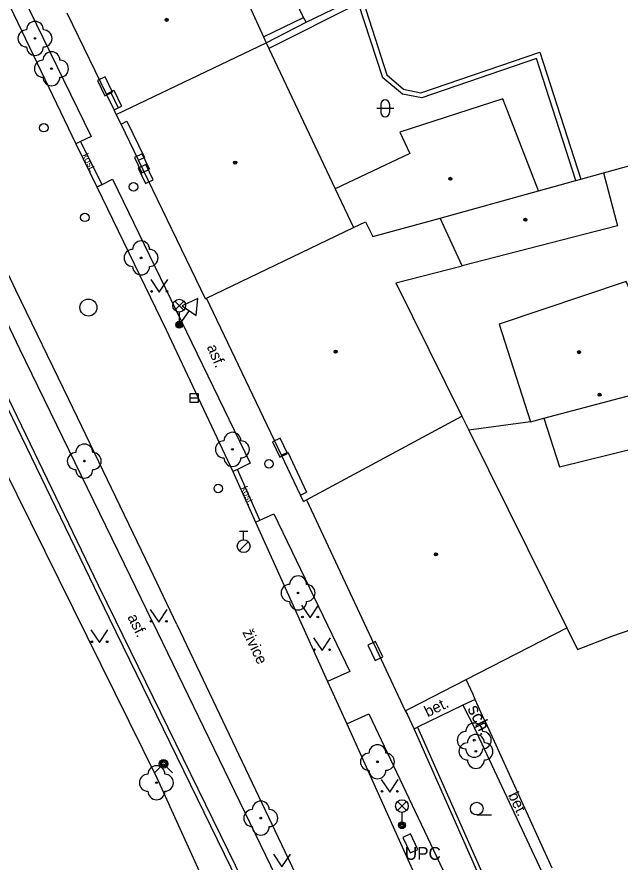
# Model space of a CAD drawing. Extents: x -595546 to -593986, y -1160845 to -1159202.
# Drawn here: x -595415.64 to -595380.17, y -1160258.12 to -1160208.45 of the extents above; entities that cross this region are included whole.
import ezdxf

# ---------------------------------------------------------------- set-up
doc = ezdxf.new("R2010")
doc.units = 0
for name, color, linetype in [('DOP - kresba z DSPS bez souradnic', 7, 'Continuous'), ('DOP - rozhrani ploch obecne', 7, 'Continuous'), ('Level 22', 7, 'Continuous'), ('Level 24', 7, 'Continuous'), ('Level 27', 7, 'Continuous'), ('Level 28', 7, 'Continuous'), ('Level 31', 7, 'Continuous'), ('Level 33', 7, 'Continuous'), ('Level 34', 7, 'Continuous'), ('Level 36', 7, 'Continuous'), ('Level 39', 7, 'Continuous'), ('TM - budovy zdene_ betonove - NP', 7, 'Continuous'), ('TM - budovy zdene_ betonove - VP', 7, 'Continuous'), ('TM - chodniky - VP', 7, 'Continuous'), ('TM - komunikace - VP', 7, 'Continuous'), ('TM - letecke snimky - pomocna linie', 7, 'Continuous'), ('TM - plot drateny_ kovovy - VP', 7, 'Continuous'), ('TM - plot nerozliseny - VP', 7, 'Continuous'), ('TM - podezdivka plotu - VP', 7, 'Continuous'), ('TM - popis objektu', 7, 'Continuous'), ('TM - popis povrchu', 7, 'Continuous'), ('TM - poznamka', 7, 'Continuous'), ('TM - rozhrani mezi zpev. plochami mezi sebou - VP', 7, 'Continuous'), ('TM - rozhrani ploch obecne - VP', 7, 'Continuous'), ('TM - schody - NP', 7, 'Continuous'), ('TM - vjezd na pozemek', 7, 'Continuous')]:
    doc.layers.add(name, color=color, linetype=linetype)

msp = doc.modelspace()

# ---------------------------------------------------------------- linework, layer by layer
at = {"layer": 'DOP - kresba z DSPS bez souradnic'}
for points in [[(-595398.78, -1160208.48), (-595401.52, -1160202.77)], [(-595395.55, -1160207.66), (-595400.82, -1160210.3)], [(-595394.13, -1160212.03), (-595395.55, -1160207.66)], [(-595401.14, -1160209.62), (-595398.78, -1160208.48)], [(-595398.64, -1160208.76), (-595398.78, -1160208.48)], [(-595385.08, -1160210.89), (-595391.83, -1160213.2)], [(-595382.77, -1160218.07), (-595385.08, -1160210.89)], [(-595392.96, -1160212.98), (-595394.13, -1160212.03)], [(-595391.83, -1160213.2), (-595392.96, -1160212.98)]]:
    msp.add_lwpolyline(points, dxfattribs=at)
at = {"layer": 'DOP - rozhrani ploch obecne'}
for points in [[(-595398.64, -1160208.76), (-595395.41, -1160207.19)], [(-595395.28, -1160207.53), (-595393.89, -1160211.85)], [(-595400.98, -1160209.97), (-595398.64, -1160208.76)], [(-595391.89, -1160212.91), (-595384.89, -1160210.51)], [(-595384.89, -1160210.51), (-595382.47, -1160217.99)], [(-595393.89, -1160211.85), (-595392.9, -1160212.69)], [(-595392.9, -1160212.69), (-595391.89, -1160212.91)], [(-595381.14, -1160217.61), (-595377.66, -1160216.65)]]:
    msp.add_lwpolyline(points, dxfattribs=at)
at = {"layer": 'Level 22'}
for centre in [(-595414.58, -1160209.71), (-595413.61, -1160211.49), (-595408.34, -1160222.61), (-595402.97, -1160233.86), (-595411.68, -1160234.55), (-595399.11, -1160242.3), (-595388.75, -1160250.95), (-595388.65, -1160251.61), (-595394.44, -1160252.22), (-595407.44, -1160253.45), (-595401.3, -1160255.53)]:
    msp.add_circle(centre, 0.05, dxfattribs=at)
for centre, start, end in [((-595414.58, -1160209.21), 0, 180), ((-595415.08, -1160209.71), 90, 270), ((-595414.08, -1160209.71), 270, 90), ((-595414.58, -1160210.21), 180, 0), ((-595413.61, -1160210.99), 0, 180), ((-595414.11, -1160211.49), 90, 270), ((-595413.11, -1160211.49), 270, 90), ((-595413.61, -1160211.99), 180, 0), ((-595408.34, -1160222.11), 0, 180), ((-595408.84, -1160222.61), 90, 270), ((-595407.84, -1160222.61), 270, 90), ((-595408.34, -1160223.11), 180, 0), ((-595402.97, -1160233.36), 0, 180), ((-595411.68, -1160234.05), 0, 180), ((-595403.47, -1160233.86), 90, 270), ((-595402.47, -1160233.86), 270, 90), ((-595412.18, -1160234.55), 90, 270), ((-595411.18, -1160234.55), 270, 90), ((-595402.97, -1160234.36), 180, 0), ((-595411.68, -1160235.05), 180, 0), ((-595399.11, -1160241.8), 0, 180), ((-595399.61, -1160242.3), 90, 270), ((-595398.61, -1160242.3), 270, 90), ((-595399.11, -1160242.8), 180, 0), ((-595388.75, -1160250.45), 0, 180), ((-595389.25, -1160250.95), 90, 270), ((-595388.25, -1160250.95), 270, 90), ((-595388.65, -1160251.11), 0, 180), ((-595394.44, -1160251.72), 0, 180), ((-595389.15, -1160251.61), 90, 270), ((-595388.75, -1160251.45), 180, 0), ((-595388.15, -1160251.61), 270, 90), ((-595394.94, -1160252.22), 90, 270), ((-595393.94, -1160252.22), 270, 90), ((-595407.44, -1160252.95), 0, 180), ((-595388.65, -1160252.11), 180, 0), ((-595407.94, -1160253.45), 90, 270), ((-595406.94, -1160253.45), 270, 90), ((-595394.44, -1160252.72), 180, 0), ((-595407.44, -1160253.95), 180, 0), ((-595401.3, -1160255.03), 0, 180), ((-595401.8, -1160255.53), 90, 270), ((-595400.8, -1160255.53), 270, 90), ((-595401.3, -1160256.03), 180, 0)]:
    msp.add_arc(centre, 0.5, start, end, dxfattribs=at)
at = {"layer": 'Level 24'}
for points in [[(-595410.906, -1160212.191), (-595410.468, -1160213.09), (-595410.019, -1160212.871), (-595410.457, -1160211.972)], [(-595408.736, -1160216.717), (-595408.304, -1160217.619), (-595407.853, -1160217.403), (-595408.285, -1160216.501)], [(-595408.504, -1160217.328), (-595408.072, -1160218.23), (-595407.621, -1160218.014), (-595408.053, -1160217.112)], [(-595400.604, -1160233.417), (-595400.173, -1160234.32), (-595399.722, -1160234.104), (-595400.153, -1160233.202)], [(-595395.002, -1160245.365), (-595394.576, -1160246.27), (-595394.123, -1160246.057), (-595394.55, -1160245.152)], [(-595392.952, -1160256.676), (-595392.525, -1160257.58), (-595392.073, -1160257.366), (-595392.5, -1160256.462)]]:
    msp.add_lwpolyline(points, close=True, dxfattribs=at)
at = {"layer": 'Level 27'}
msp.add_line((-595405.47, -1160230.84), (-595404.97, -1160230.84), dxfattribs=at)
msp.add_lwpolyline([(-595405.47, -1160231.09), (-595404.97, -1160231.09), (-595404.97, -1160230.59), (-595405.47, -1160230.59)], close=True, dxfattribs=at)
msp.add_circle((-595411.44, -1160225.53), 0.5, dxfattribs=at)
at = {"layer": 'Level 28'}
for p, q in [((-595402.56, -1160238.675), (-595402.06, -1160238.675)), ((-595402.31, -1160239.175), (-595402.31, -1160238.675)), ((-595402.568, -1160239.822), (-595402.038, -1160239.292))]:
    msp.add_line(p, q, dxfattribs=at)
for centre, radius in [((-595414.06, -1160214.96), 0.25), ((-595408.79, -1160218.43), 0.25), ((-595411.65, -1160220.23), 0.25), ((-595400.82, -1160234.71), 0.25), ((-595403.8, -1160236.16), 0.25), ((-595402.31, -1160239.55), 0.375)]:
    msp.add_circle(centre, radius, dxfattribs=at)
at = {"layer": 'Level 31'}
msp.add_lwpolyline([(-595407.55, -1160252.87), (-595407.02, -1160252.34), (-595406.49, -1160252.87)], dxfattribs=at)
for radius in [0.25, 0.18, 0.11]:
    msp.add_circle((-595407.02, -1160252.34), radius, dxfattribs=at)
at = {"layer": 'Level 33'}
for p, q in [((-595406.365, -1160225.68), (-595405.835, -1160225.15)), ((-595406.365, -1160225.15), (-595405.835, -1160225.68)), ((-595406.1, -1160225.79), (-595406.1, -1160226.54)), ((-595393.265, -1160255.09), (-595392.735, -1160254.56)), ((-595393.265, -1160254.56), (-595392.735, -1160255.09)), ((-595393, -1160255.2), (-595393, -1160255.95))]:
    msp.add_line(p, q, dxfattribs=at)
for centre, radius in [((-595406.1, -1160225.415), 0.375), ((-595406.1, -1160226.54), 0.2), ((-595406.1, -1160226.54), 0.145), ((-595406.1, -1160226.54), 0.0876), ((-595393, -1160254.825), 0.375), ((-595393, -1160255.95), 0.2), ((-595393, -1160255.95), 0.145), ((-595393, -1160255.95), 0.0876)]:
    msp.add_circle(centre, radius, dxfattribs=at)
at = {"layer": 'Level 34'}
for p, q in [((-595405.513, -1160225.708), (-595406.1, -1160226.54)), ((-595406.304, -1160226.396), (-595405.896, -1160226.684))]:
    msp.add_line(p, q, dxfattribs=at)
msp.add_lwpolyline([(-595405.921, -1160225.42), (-595405.104, -1160225.997), (-595405.013, -1160225.001)], close=True, dxfattribs=at)
at = {"layer": 'Level 36'}
for p, q in [((-595394.236, -1160213.566), (-595394.236, -1160214.066)), ((-595393.736, -1160213.566), (-595393.736, -1160214.066)), ((-595394.486, -1160213.816), (-595393.486, -1160213.816)), ((-595388.6, -1160255.345), (-595387.725, -1160255.345))]:
    msp.add_line(p, q, dxfattribs=at)
for points in [[(-595407.77, -1160223.88), (-595407.27, -1160224.63), (-595406.77, -1160223.88)], [(-595398.9, -1160243.01), (-595398.4, -1160243.76), (-595397.9, -1160243.01)], [(-595407.8, -1160243.27), (-595407.3, -1160244.02), (-595406.8, -1160243.27)], [(-595411.29, -1160244.47), (-595410.79, -1160245.22), (-595410.29, -1160244.47)], [(-595398.2, -1160244.94), (-595397.7, -1160245.69), (-595397.2, -1160244.94)], [(-595394.22, -1160253.26), (-595393.72, -1160254.01), (-595393.22, -1160253.26)], [(-595400.56, -1160257.64), (-595400.06, -1160258.39), (-595399.56, -1160257.64)]]:
    msp.add_lwpolyline(points, dxfattribs=at)
for centre, radius in [((-595407.72, -1160224.58), 0.05), ((-595406.821, -1160224.58), 0.05), ((-595407.75, -1160243.97), 0.05), ((-595406.851, -1160243.97), 0.05), ((-595398.85, -1160243.71), 0.05), ((-595397.951, -1160243.71), 0.05), ((-595411.24, -1160245.17), 0.05), ((-595410.341, -1160245.17), 0.05), ((-595398.15, -1160245.64), 0.05), ((-595397.251, -1160245.64), 0.05), ((-595394.17, -1160253.96), 0.05), ((-595393.271, -1160253.96), 0.05), ((-595388.6, -1160254.97), 0.375)]:
    msp.add_circle(centre, radius, dxfattribs=at)
for centre, start, end in [((-595393.986, -1160213.566), 0, 180), ((-595393.986, -1160214.066), 180, 0)]:
    msp.add_arc(centre, 0.25, start, end, dxfattribs=at)
at = {"layer": 'Level 39'}
for centre, radius in [((-595406.84, -1160208.62), 0.09), ((-595406.84, -1160208.62), 0.0398), ((-595402.81, -1160217.01), 0.09), ((-595402.81, -1160217.01), 0.0398), ((-595390.15, -1160217.96), 0.09), ((-595390.15, -1160217.96), 0.0398), ((-595385.74, -1160220.37), 0.09), ((-595385.74, -1160220.37), 0.0398), ((-595396.9, -1160228.12), 0.09), ((-595396.9, -1160228.12), 0.0398), ((-595382.58, -1160228.15), 0.09), ((-595382.58, -1160228.15), 0.0398), ((-595381.38, -1160230.65), 0.09), ((-595381.38, -1160230.65), 0.0398), ((-595391, -1160240.03), 0.09), ((-595391, -1160240.03), 0.0398)]:
    msp.add_circle(centre, radius, dxfattribs=at)
at = {"layer": 'TM - budovy zdene_ betonove - NP'}
for points in [[(-595410.38, -1160212.98), (-595409.94, -1160212.76)], [(-595409.94, -1160212.76), (-595409.49, -1160213.69)], [(-595409.93, -1160213.91), (-595409.49, -1160213.69)], [(-595409.52, -1160214.75), (-595409.17, -1160214.58)], [(-595409.17, -1160214.58), (-595408.15, -1160216.7)], [(-595408.49, -1160216.87), (-595408.15, -1160216.7)], [(-595400.09, -1160234.21), (-595399.72, -1160234.03)], [(-595399.72, -1160234.03), (-595398.61, -1160236.37)], [(-595398.97, -1160236.55), (-595398.61, -1160236.37)]]:
    msp.add_lwpolyline(points, dxfattribs=at)
at = {"layer": 'TM - budovy zdene_ betonove - VP'}
for points in [[(-595403.73, -1160203.93), (-595401.14, -1160209.62)], [(-595410.38, -1160212.98), (-595412.69, -1160208.22)], [(-595401.14, -1160209.62), (-595400.98, -1160209.97)], [(-595409.8, -1160214.18), (-595400.98, -1160209.97)], [(-595400.98, -1160209.97), (-595400.82, -1160210.3)], [(-595400.82, -1160210.3), (-595396.92, -1160218.55)], [(-595409.93, -1160213.91), (-595410.38, -1160212.98)], [(-595387.06, -1160213.26), (-595393.12, -1160215.23)], [(-595384.97, -1160218.67), (-595387.06, -1160213.26)], [(-595409.8, -1160214.18), (-595409.93, -1160213.91)], [(-595409.52, -1160214.75), (-595409.8, -1160214.18)], [(-595408.49, -1160216.87), (-595409.52, -1160214.75)], [(-595393.12, -1160215.23), (-595392.54, -1160216.47)], [(-595392.54, -1160216.47), (-595396.92, -1160218.55)], [(-595404.55, -1160225.01), (-595408.49, -1160216.87)], [(-595382.47, -1160217.99), (-595381.14, -1160217.61)], [(-595381.14, -1160217.61), (-595380.32, -1160220.73)], [(-595384.97, -1160218.67), (-595382.77, -1160218.07)], [(-595382.77, -1160218.07), (-595382.47, -1160217.99)], [(-595396.92, -1160218.55), (-595395.84, -1160220.82)], [(-595390.76, -1160220.27), (-595384.97, -1160218.67)], [(-595395.84, -1160220.82), (-595395.15, -1160220.49)], [(-595395.15, -1160220.49), (-595394.71, -1160221.35)], [(-595394.71, -1160221.35), (-595390.76, -1160220.27)], [(-595389.45, -1160223.07), (-595390.76, -1160220.27)], [(-595380.32, -1160220.73), (-595389.45, -1160223.07)], [(-595404.49, -1160224.98), (-595395.84, -1160220.82)], [(-595393.36, -1160224.07), (-595389.45, -1160223.07)], [(-595393.36, -1160224.07), (-595389.47, -1160231.91)], [(-595404.55, -1160225.01), (-595404.49, -1160224.98)], [(-595400.09, -1160234.21), (-595404.49, -1160224.98)], [(-595398.61, -1160236.83), (-595389.47, -1160231.91)], [(-595389.47, -1160231.91), (-595389.06, -1160232.74)], [(-595389.06, -1160232.74), (-595383.31, -1160244.34)], [(-595398.97, -1160236.55), (-595400.09, -1160234.21)], [(-595398.78, -1160236.92), (-595398.97, -1160236.55)], [(-595398.78, -1160236.92), (-595398.61, -1160236.83)], [(-595398.61, -1160236.83), (-595392.81, -1160249.22)], [(-595389.23, -1160247.38), (-595383.31, -1160244.34)], [(-595383.31, -1160244.34), (-595382.68, -1160245.62)], [(-595380.65, -1160244.83), (-595379.41, -1160244.41)], [(-595382.68, -1160245.62), (-595380.65, -1160244.83)], [(-595392.81, -1160249.22), (-595392.54, -1160249.08), (-595389.23, -1160247.38)], [(-595388.82, -1160248.27), (-595389.23, -1160247.38)], [(-595388.69, -1160248.56), (-595388.82, -1160248.27)], [(-595388.16, -1160249.73), (-595388.69, -1160248.56)], [(-595388.07, -1160249.92), (-595388.16, -1160249.73)], [(-595384.17, -1160258.48), (-595388.07, -1160249.92)]]:
    msp.add_lwpolyline(points, dxfattribs=at)
at = {"layer": 'TM - chodniky - VP'}
for points in [[(-595416.14, -1160205.51), (-595411.28, -1160215.47), (-595411.9, -1160215.77)], [(-595407.69, -1160243.96), (-595408.96, -1160241.34), (-595415.47, -1160227.98), (-595419.11, -1160220.36), (-595422.5, -1160213.46)], [(-595409.82, -1160243.94), (-595410.84, -1160241.86), (-595417.38, -1160228.35), (-595421.14, -1160220.47), (-595424.27, -1160214.19)], [(-595411.9, -1160215.77), (-595412.17, -1160215.9)], [(-595410.63, -1160218.29), (-595410.02, -1160217.99), (-595401.93, -1160234.68), (-595402.67, -1160235.04)], [(-595410.94, -1160218.44), (-595410.63, -1160218.29)], [(-595402.67, -1160235.04), (-595402.95, -1160235.17)], [(-595401.61, -1160238.14), (-595401.36, -1160238.03)], [(-595401.36, -1160238.03), (-595400.53, -1160237.65), (-595396.07, -1160246.92), (-595397.37, -1160247.51)], [(-595407.69, -1160243.96), (-595396.79, -1160266.44)], [(-595389.42, -1160248.89), (-595392.09, -1160250.19)], [(-595388.69, -1160248.56), (-595389.42, -1160248.89)], [(-595396.25, -1160250), (-595394.95, -1160249.41), (-595389.33, -1160261.25)]]:
    msp.add_lwpolyline(points, dxfattribs=at)
at = {"layer": 'TM - komunikace - VP'}
for points in [[(-595416.99, -1160205.92), (-595412.17, -1160215.9)], [(-595406.23, -1160244.16), (-595407.81, -1160240.86), (-595412.6, -1160230.93), (-595415.7, -1160224.5), (-595417.62, -1160220.47), (-595421.31, -1160212.96)], [(-595412.17, -1160215.9), (-595410.94, -1160218.44)], [(-595410.94, -1160218.44), (-595406.86, -1160226.84), (-595402.95, -1160235.17)], [(-595402.95, -1160235.17), (-595401.61, -1160238.14)], [(-595401.61, -1160238.14), (-595397.37, -1160247.51)], [(-595406.23, -1160244.16), (-595395.84, -1160265.98)], [(-595397.37, -1160247.51), (-595396.25, -1160250)], [(-595396.25, -1160250), (-595390.88, -1160261.89)]]:
    msp.add_lwpolyline(points, dxfattribs=at)
at = {"layer": 'TM - letecke snimky - pomocna linie'}
for points in [[(-595377.09, -1160230.03), (-595379.81, -1160223.99), (-595387.29, -1160226.51), (-595385.44, -1160232.24)], [(-595384.66, -1160232.03), (-595383.74, -1160234.88), (-595375.96, -1160232.97), (-595376.75, -1160229.9)], [(-595384.66, -1160232.03), (-595377.09, -1160230.03)], [(-595385.44, -1160232.24), (-595384.66, -1160232.03)], [(-595385.44, -1160232.24), (-595389.06, -1160232.74)]]:
    msp.add_lwpolyline(points, dxfattribs=at)
at = {"layer": 'TM - plot drateny_ kovovy - VP'}
for points in [[(-595427.32, -1160215.39), (-595425.24, -1160217.06), (-595424.72, -1160218.19), (-595407.41, -1160253.16), (-595402.86, -1160263.18)], [(-595392.09, -1160250.19), (-595387.7, -1160260.08)]]:
    msp.add_lwpolyline(points, dxfattribs=at)
at = {"layer": 'TM - plot nerozliseny - VP'}
msp.add_lwpolyline([(-595392.81, -1160249.22), (-595392.68, -1160249.45)], dxfattribs=at)
at = {"layer": 'TM - podezdivka plotu - VP'}
for points in [[(-595398.67, -1160267.4), (-595410.2, -1160243.8)], [(-595398.38, -1160267.32), (-595409.82, -1160243.94)], [(-595392.29, -1160250.28), (-595392.09, -1160250.19)], [(-595387.61, -1160260.83), (-595392.29, -1160250.28)]]:
    msp.add_lwpolyline(points, dxfattribs=at)
at = {"layer": 'TM - rozhrani mezi zpev. plochami mezi sebou - VP'}
for points in [[(-595410.63, -1160218.29), (-595411.9, -1160215.77)], [(-595401.36, -1160238.03), (-595402.67, -1160235.04)]]:
    msp.add_lwpolyline(points, dxfattribs=at)
at = {"layer": 'TM - rozhrani ploch obecne - VP'}
for points in [[(-595410.2, -1160243.8), (-595411.09, -1160241.98), (-595417.92, -1160227.87), (-595421.39, -1160220.59), (-595424.52, -1160214.31)], [(-595389.42, -1160248.89), (-595388.74, -1160250.22)], [(-595388.07, -1160249.92), (-595388.74, -1160250.22)], [(-595384.76, -1160258.7), (-595388.74, -1160250.22)]]:
    msp.add_lwpolyline(points, dxfattribs=at)
at = {"layer": 'TM - schody - NP'}
msp.add_lwpolyline([(-595410.14, -1160212.86), (-595409.69, -1160213.79)], dxfattribs=at)
at = {"layer": 'TM - vjezd na pozemek'}
msp.add_lwpolyline([(-595392.29, -1160250.28), (-595392.68, -1160249.45)], dxfattribs=at)

# ---------------------------------------------------------------- texts
at = {"layer": 'TM - popis objektu'}
msp.add_text('UPC', height=0.75, dxfattribs=at).set_placement((-595392.83, -1160257.98))
at = {"layer": 'TM - popis povrchu'}
for s, height, rotation, p in [('kost.', 0.4, 296.5246, (-595411.82, -1160216.58)), ('asf.', 0.65, 293.168, (-595404.49, -1160227.84)), ('kost.', 0.4, 292.9324, (-595402.47, -1160236.13)), ('asf.', 0.65, 295.9528, (-595409.16, -1160243.71)), ('živice', 0.65, 295.659, (-595402.4, -1160244.6)), ('bet.', 0.65, 25.8419, (-595391.49, -1160249.61)), ('bet.', 0.65, 295.1425, (-595386.77, -1160254.17))]:
    msp.add_text(s, height=height, rotation=rotation, dxfattribs=at).set_placement(p)
at = {"layer": 'TM - poznamka'}
msp.add_text('sch.', height=0.75, rotation=297.0797, dxfattribs=at).set_placement((-595389.17, -1160249.1))

doc.saveas('drawing.dxf')
